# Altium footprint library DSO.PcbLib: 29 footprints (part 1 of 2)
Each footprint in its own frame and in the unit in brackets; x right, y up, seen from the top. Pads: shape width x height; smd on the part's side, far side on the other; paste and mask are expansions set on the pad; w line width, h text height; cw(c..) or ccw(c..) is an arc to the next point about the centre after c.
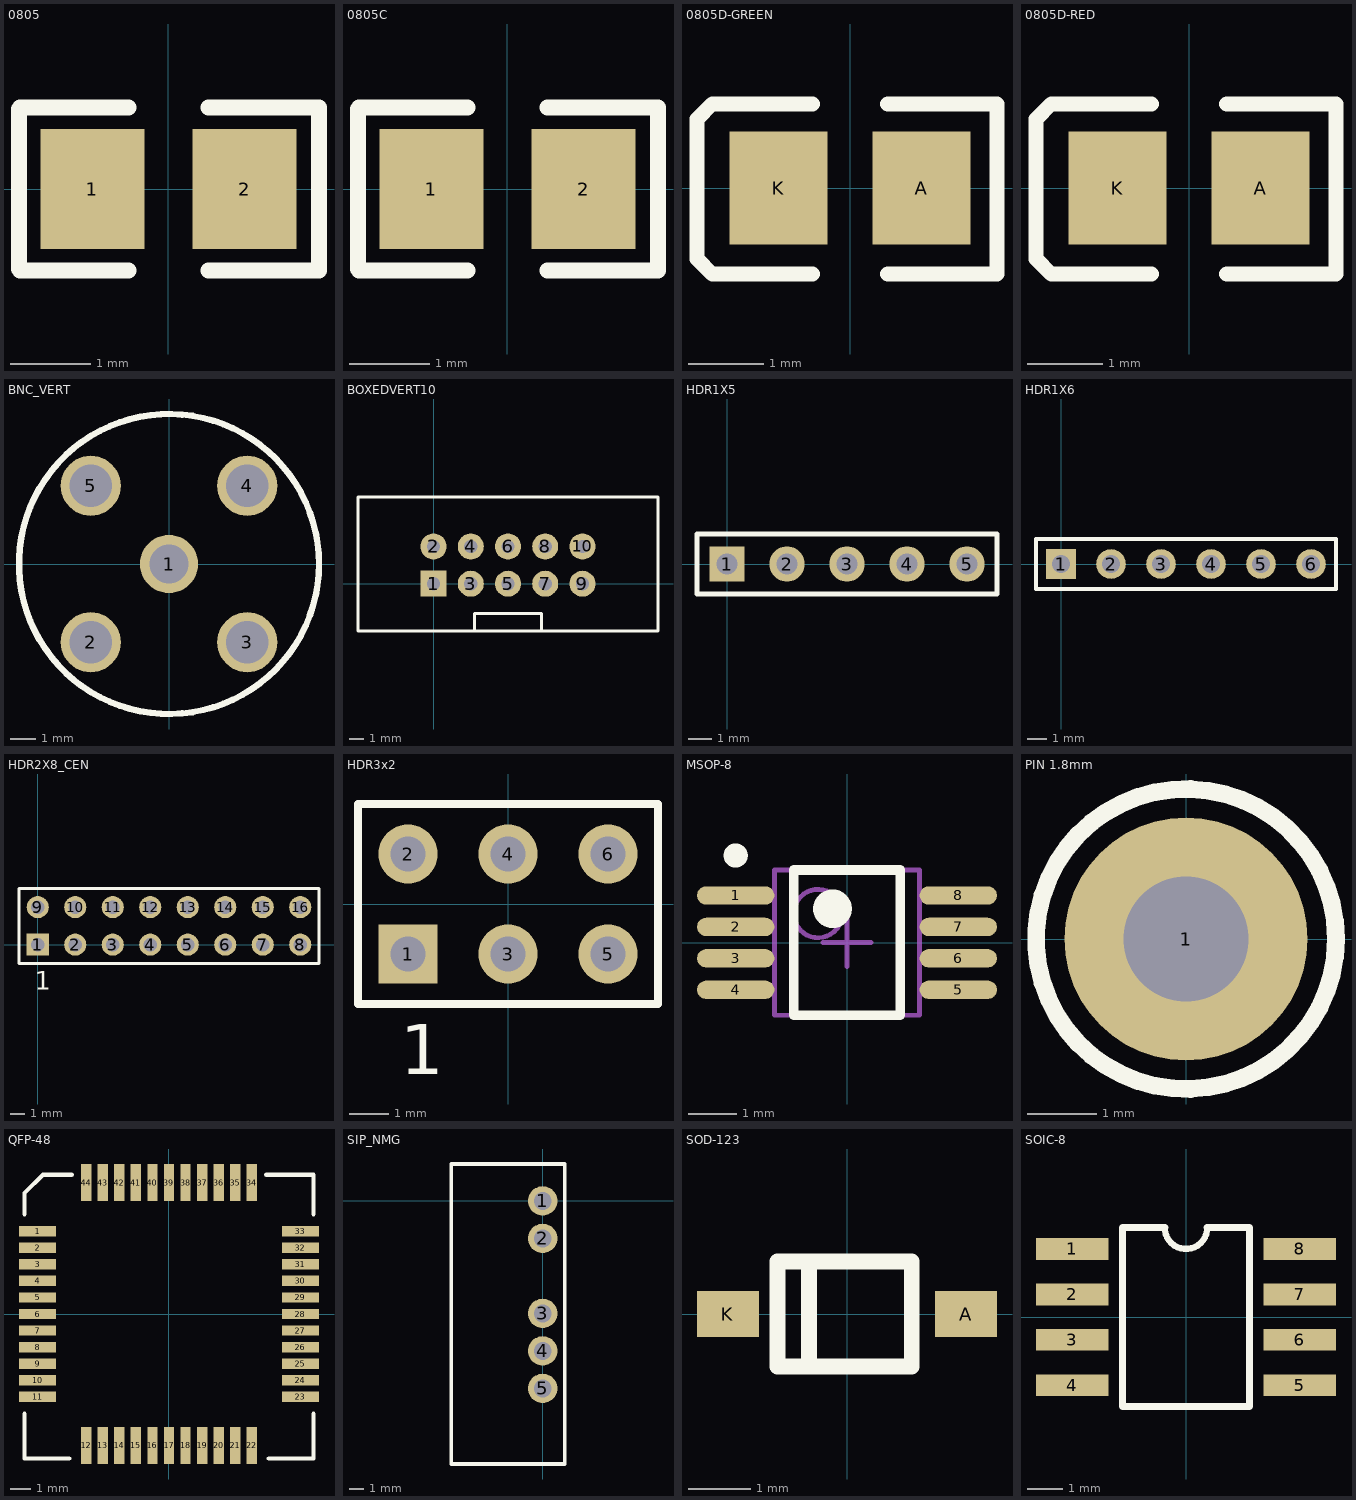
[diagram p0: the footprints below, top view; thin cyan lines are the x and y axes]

## 0805 [mm] "0805 Footprint"
height 1
pads (2):
  rect 1.3x1.5 smd: 1(-0.95,0) 2(0.95,0)
Top Overlay:
  lines w0.2: -1.867,-1 -1.867,1 ; -1.854,-1.016 -0.5,-1.016 ; -1.854,1.016 -0.5,1.016 ; 0.5,-1.016 1.88,-1.016 ; 0.5,1.016 1.88,1.016 ; 1.88,-1 1.88,1
3D body "RES0805.stp": height 0.5, standoff 0, extent -1,-0.63 1,0.62

## 0805C [mm] "0805 Footprint"
height 1
pads (2):
  rect 1.3x1.5 smd: 1(-0.95,0) 2(0.95,0)
Top Overlay:
  lines w0.2: -1.867,-1 -1.867,1 ; -1.854,-1.016 -0.5,-1.016 ; -1.854,1.016 -0.5,1.016 ; 0.5,-1.016 1.88,-1.016 ; 0.5,1.016 1.88,1.016 ; 1.88,-1 1.88,1
3D body "CAP0805.stp": height 0.78, standoff 0, extent -1,-0.625 1,0.625

## 0805D-GREEN [mm] "0805 Diode"
height 1
pads (2):
  rect 1.3x1.5 smd: A(0.95,0) K(-0.95,0)
Top Overlay:
  lines w0.2: -0.5,-1.143 -1.829,-1.143 -2.032,-0.94 -2.032,0.914 -1.829,1.118 -0.5,1.118 ; 0.5,-1.143 1.95,-1.143 1.95,1.118 0.5,1.118
3D body "User Library-led_0805.step": height 1.1, standoff 0, extent -1.01,-0.625 1.01,0.625

## 0805D-RED [mm] "0805 Diode RED"
height 1
pads (2):
  rect 1.3x1.5 smd: A(0.95,0) K(-0.95,0)
Top Overlay:
  lines w0.2: -0.5,-1.143 -1.829,-1.143 -2.032,-0.94 -2.032,0.914 -1.829,1.118 -0.5,1.118 ; 0.5,-1.143 1.95,-1.143 1.95,1.118 0.5,1.118
3D body "LED-0805-RED.STEP": height 0.9, standoff -0.01, extent -1.05,-0.675 1.05,0.675

## BNC_VERT [mil] "BNC vertical connector"
height 539.37
pads (5):
  round 92 hole 62: 1(0,0)
  round 95 hole 67: 2(-123.23,-123.23) 3(123.23,-123.23) 4(123.23,123.23) 5(-123.23,123.23)
Top Overlay:
  circle w10: c0,0 r236.22
3D body "BNC Connector.stp": height 539.37, standoff -192.91, extent -216.53,-216.92 216.54,216.93

## BOXEDVERT10 [mil] "IDC Header 2.54mm Boxed 10 pins"
height 346.46
pads (10):
  rect 70x70 hole 35.43: 1(0,0)
  round 70 hole 35.43: 2(0,100) 3(100,0) 4(100,100) 5(200,0) 6(200,100) 7(300,0) 8(300,100) 9(400,0) 10(400,100)
Top Overlay:
  lines w7.87: 110,-123.31 110,-80 290,-80 290,-123.31 ; -203,-126.5 -203,232.41 603,232.41 603,-126.5 -203,-126.5
3D body "User Library-BH-10__64 (3).step": height 358.87, standoff -117.51, extent -203.54,-129.13 603.55,237.01

## HDR1X5 [mm] "Connector; Header; 5 Position"
pads (5):
  rect 1.5x1.5 hole 0.9: 1(0,0)
  round 1.5 hole 0.9: 2(2.54,0) 3(5.08,0) 4(7.62,0) 5(10.16,0)
Top Overlay:
  lines w0.2: -1.27,-1.27 -1.27,1.27 11.43,1.27 11.43,-1.27 -1.27,-1.27

## HDR1X6 [mm] "Connector; Header; 6 Position"
pads (6):
  rect 1.5x1.5 hole 0.9: 1(0,0)
  round 1.5 hole 0.9: 2(2.54,0) 3(5.08,0) 4(7.62,0) 5(10.16,0) 6(12.7,0)
Top Overlay:
  lines w0.2: -1.27,-1.27 -1.27,1.27 13.97,1.27 13.97,-1.27 -1.27,-1.27

## HDR2X8_CEN [mm] "Connector; Header; 8x2 Position"
pads (16):
  rect 1.5x1.5 hole 0.9: 1(0,0)
  round 1.5 hole 0.9: 2(2.54,0) 3(5.08,0) 4(7.62,0) 5(10.16,0) 6(12.7,0) 7(15.24,0) 8(17.78,0) 9(0,2.54) 10(2.54,2.54) 11(5.08,2.54) 12(7.62,2.54) 13(10.16,2.54) 14(12.7,2.54) 15(15.24,2.54) 16(17.78,2.54)
Top Overlay:
  lines w0.2: -1.27,-1.27 19.05,-1.27 19.05,3.81 -1.27,3.81 -1.27,-1.27
  text "1" at -0.203,-3.048 h1.27

## HDR3x2 [mm] "Connector; Header; 8x2 Position"
pads (6):
  rect 1.5x1.5 hole 0.9: 1(-2.54,-1.27)
  round 1.5 hole 0.9: 2(-2.54,1.27) 3(0,-1.27) 4(0,1.27) 5(2.54,-1.27) 6(2.54,1.27)
Top Overlay:
  lines w0.2: -3.81,-2.54 -3.81,2.54 3.81,2.54 3.81,-2.54 -3.81,-2.54
  text "1" at -2.743,-4.318 h1.27
3D body "Pin Header 2x3 TH Pitch 2.54mm.stp": height 9.5, standoff -3.2, extent -3.81,-2.54 3.81,2.54

## MSOP-8 [mm] "TSOP, 8-Leads, Body 3.00x3.00mm, Pitch 0.65mm, IPC Low Density"
height 1.1
pads (8):
  oval 1.6x0.38 smd: 1(-2.3,0.975) 2(-2.3,0.325) 3(-2.3,-0.325) 4(-2.3,-0.975) 5(2.3,-0.975) 6(2.3,-0.325) 7(2.3,0.325) 8(2.3,0.975)
Top Overlay:
  circle w0.25: c-2.3,1.8 r0.125
  circle w0.4: c-0.3,0.7 r0.2
  lines w0.2: -1.1,-1.5 -1.1,1.5 1.1,1.5 1.1,-1.5 -1.1,-1.5
Mechanical 13:
  circle w0.1: c-0.6,0.6 r0.5
  lines w0.1: -1.5,-1.5 -1.5,1.5 1.5,1.5 1.5,-1.5 -1.5,-1.5
Mechanical 15:
  lines w0.1: -0.5,0 0.5,0 ; 0,-0.5 0,0.5
3D body "TSOP65P490X110-8M.step": height 1.1, standoff 0, extent -2.45,-1.5 2.45,1.5

## PIN 1.8mm [mm] "Single Pin"
height 10
pads (1):
  round 3.5 hole 1.8: 1(0,0)
Top Overlay:
  circle w0.254: c0,0 r2.159

## QFP-48 [mm]
height 1
pads (44):
  rect 1.8x0.5 smd: 1(-6.35,4) 2(-6.35,3.2) 3(-6.35,2.4) 4(-6.35,1.6) 5(-6.35,0.8) 6(-6.35,0) 7(-6.35,-0.8) 8(-6.35,-1.6) 9(-6.35,-2.4) 10(-6.35,-3.2) 11(-6.35,-4) 23(6.35,-4) 24(6.35,-3.2) 25(6.35,-2.4) 26(6.35,-1.6) 27(6.35,-0.8) 28(6.35,0) 29(6.35,0.8) 30(6.35,1.6) 31(6.35,2.4) 32(6.35,3.2) 33(6.35,4)
  rect 0.5x1.8 smd: 12(-4,-6.35) 13(-3.2,-6.35) 14(-2.4,-6.35) 15(-1.6,-6.35) 16(-0.8,-6.35) 17(0,-6.35) 18(0.8,-6.35) 19(1.6,-6.35) 20(2.4,-6.35) 21(3.2,-6.35) 22(4,-6.35) 34(4,6.35) 35(3.2,6.35) 36(2.4,6.35) 37(1.6,6.35) 38(0.8,6.35) 39(0,6.35) 40(-0.8,6.35) 41(-1.6,6.35) 42(-2.4,6.35) 43(-3.2,6.35) 44(-4,6.35)
Top Overlay:
  lines w0.203: -6.985,-4.826 -6.985,-6.985 -4.826,-6.985 ; -6.985,4.826 -6.985,5.842 -6.096,6.731 -4.699,6.731 ; 4.699,6.731 6.985,6.731 6.985,4.826 ; 4.826,-6.985 6.985,-6.985 6.985,-4.826
3D body "User Library-44 pin tqfp ic package.step": height 1.13, standoff 0.02, extent -5.974,-6 6.026,6

## SIP_NMG [mm] "SIP for NMG DC to DC"
height 7.65
pads (5):
  round 2 hole 1.2: 1(0,0) 2(0,-2.54) 3(0,-7.62) 4(0,-10.16) 5(0,-12.7)
Top Overlay:
  lines w0.254: -6.2,-17.82 -6.2,2.5 1.5,2.5 1.5,-17.82 -6.2,-17.82
3D body: height 10.2, standoff 0, extent -6.2,-17.8 1.5,2.5

## SOD-123 [mm] "SMD diode"
height 1.35
pads (2):
  rect 1x0.75 smd: A(1.925,0) K(-1.925,0)
Top Overlay:
  lines w0.254: -0.615,-0.85 -0.615,0.85 ; 1.036,-0.85 -1.123,-0.85 -1.123,0.85 1.036,0.85 ; 1.049,-0.85 1.049,0.85
3D body "User Library-SOD-123_DiodesInc.STEP": height 1.42, standoff -0.03, extent -1.93,-0.862 1.92,0.838

## SOIC-8 [mil] "SOIC-8 Footprint"
height 68.9
pads (8):
  rect 80x24 smd: 1(-125,75) 2(-125,25) 3(-125,-25) 4(-125,-75) 5(125,-75) 6(125,-25) 7(125,25) 8(125,75)
Top Overlay:
  lines w7: -23.43,98.42 ccw(c0,98.42) 23.43,98.42
  lines w7.87: -23.43,98.43 -70,98.43 -70,-98.43 70,-98.43 70,98.43 23.43,98.43
3D body "SOIC127P600X175-8N.step": height 68.98, standoff 0, extent -117.99,-98.43 117.99,98.43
